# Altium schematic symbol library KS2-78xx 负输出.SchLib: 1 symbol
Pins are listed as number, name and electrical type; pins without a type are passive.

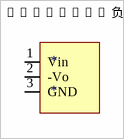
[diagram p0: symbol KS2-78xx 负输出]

## KS2-78xx 负输出
designator *
footprint Model Name (Footprint not found)
pins: 1 Vin, 2 -Vo, 3 GND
